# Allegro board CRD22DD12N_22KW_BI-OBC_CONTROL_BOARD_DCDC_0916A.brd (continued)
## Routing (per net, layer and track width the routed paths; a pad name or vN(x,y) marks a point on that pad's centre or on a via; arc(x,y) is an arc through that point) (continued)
DCPWM2A_2L: length 20.6
  TOP w0.152: v1(62.23,35.43) 61.66,34.86 60.64,34.86 60.07,34.29 U58.2
  BOTTOM w0.152: v1(62.23,35.43) 62.23,36.2 65.41,39.37 65.41,47 J3.5
DCPWM2A_2LL: length 30.2
  TOP w0.152: U58.1 60.68,35.56 60.96,35.84 v1(60.96,36.83) ; v1(43.69,41.78) 43.31,41.4 43.31,40.26 43.56,40.01 43.56,38.1 43.43,37.98 R421.2
  ART03 w0.127: v1(60.96,36.83) 60.12,36.83 57.43,39.52 45.44,39.52 44.42,40.54 44.42,41.05 v1(43.69,41.78)
  BOTTOM w0.152: U28.166 43.22,41.31 v1(43.69,41.78)
DCSHORT: length 38.6
  ART03 w0.127: v1(53.21,36.83) 54.79,36.83 56.51,35.11 57.99,35.11 60.58,32.51 63.63,32.51 69.22,38.1 v1(69.22,38.23)
  BOTTOM w0.152: v1(69.22,38.23) 69.85,37.59 69.85,33.78 69.98,33.66 73.28,33.66 73.78,33.15 R505.2 C464.1 U61.4 ; v1(53.21,36.83) 52.65,36.27 52.65,35.66 52.3,35.31 51.44,35.31 50.91,34.79 U28.5
DCVOLT1: length 8.4
  TOP w0.152: C455.2 R491.2 91.72,23.01 92.05,23.01 92.66,23.62 v1(92.66,24.03)
  BOTTOM w0.152: U44.1 93.98,25.97 93.62,25.61 92.49,25.61 91.64,24.77 R482.1 92.3,24.03 v1(92.66,24.03)
IOUT_ADC: length 94.2
  TOP w0.152: v1(58.14,10.59) 58.14,14.76 R607.1
  ART03 w0.127: v1(58.14,10.59) 57.33,9.78 55.37,9.78 54.61,10.54 54.61,11.56 53.62,12.55 39.22,12.55 38.61,11.94 38.61,11.18 36.6,9.17 25.76,9.17 22.35,12.57 18.41,12.57 14.1,16.89 14.1,39.12 18.16,43.18 18.16,48.01 J2.14
OUTPUT_OC: length 53.7
  TOP w0.152: v1(21.6,46.99) 20.96,46.99 J2.16 14.92,47.32 14.92,41.85 15.88,40.89 D95.3
  ART03 w0.127: v1(21.6,46.99) 22.23,46.35 29.21,46.35 34.16,41.4 37.08,41.4 38.53,39.95 40.64,39.95 42.71,37.88 v1(52.1,37.88)
  BOTTOM w0.152: U28.2 51.02,36.28 51.43,36.7 51.43,37.21 v1(52.1,37.88)
OUTPUT_OC_17227068: length 1.3
  TOP w0.152: R691.2 R689.2
P_ADREF3.2V: length 13.6
  TOP w0.508: C551.2 42.55,14.94 v1(42.9,15.29) ; v1(48.26,20.19) 48.39,20.32 C559.2 C558.2 ; C549.2 45.09,14.86 v1(44.71,15.23)
  BOTTOM w0.254: v1(42.9,15.29) 43.22,14.98 U28.55 ; v1(44.71,15.23) 44.22,14.73 U28.53 ; U28.35 48.67,19.79 v1(48.26,20.19) ; v1(48.26,18.03) 48.26,18.16 48.88,18.79 U28.37
  vias: v1(50.16,3.81)
P_SCL: length 32.7
  ART03 w0.127: v1(46.74,41.78) 47.24,41.27 48.51,41.27 48.86,40.93 58.38,40.93 60.83,38.48 64.9,38.48 65.79,39.37 v1(66.67,39.37)
  BOTTOM w0.152: U32.6 65.41,33.78 66.37,34.75 66.37,35.13 R438.1 67.21,35.44 67.44,35.66 67.44,38.61 v1(66.67,39.37) ; v1(46.74,41.78) 47.32,41.2 47.32,39.62 47.22,39.51 U28.174
P_SDA: length 25.4
  ART03 w0.127: v1(63.5,34.29) 63.5,35.56 61.21,37.85 60.33,37.85 58.01,40.16 47.2,40.16 v1(46.71,40.64)
  BOTTOM w0.152: U32.5 64.14,33.66 v1(63.5,34.29) 63.5,34.67 64.26,35.44 R437.1 ; v1(46.71,40.64) U28.173
P_WD_GREEN: length 13.4
  TOP w0.152: v1(40.64,42.55) 41.02,42.55 41.73,43.25 D102.2
  BOTTOM w0.152: v1(40.64,42.55) 40.31,42.87 36.96,42.87 35.96,41.87 33.05,41.87 31.71,40.54 U28.143
P_WD_RED: length 16.9
  TOP w0.152: D103.2 43.87,43.25 44.7,42.42 v1(44.7,42.29)
  BOTTOM w0.152: v1(44.7,42.29) 44.32,42.67 42.19,42.67 41.55,42.04 40.13,42.04 39.72,42.44 37.25,42.44 36.18,41.38 33.34,41.38 32.22,40.26 U28.144
PCS_ADC: length 10.9
  TOP w0.152: R602.2 40.01,7.5 40.64,8.13 v1(40.64,8.89)
  BOTTOM w0.152: U28.58 41.71,10.29 41.91,10.09 D90.3 41.91,8.64 41.78,8.51 41.02,8.51 v1(40.64,8.89) R606.1 C596.1
PCS_ADC1: length 8.2
  BOTTOM w0.152: C597.1 36.58,8.89 R606.2 37.98,9.53 39.12,10.67 40.77,10.67 41.22,11.12 U28.59
PWM1A: length 43.1
  TOP w0.152: U62.8 65.66,38.1 66.42,38.86 67.06,38.86 67.18,38.99 67.18,40.13 v1(66.67,40.64)
  ART03 w0.152: J2.1 39.38,48.9 62.1,48.9 67.18,43.81 67.18,41.15 v1(66.67,40.64)
PWM1AA: length 27.5
  TOP w0.152: U62.9 64.39,39.37 63.75,40.01 62.48,40.01 62.23,40.26 62.23,42.55 v1(62.87,43.18) ; R414.2 v1(53.34,34.29)
  BOTTOM w0.152: v1(62.87,43.18) 61.14,43.18 57.76,39.8 57.76,35.49 56.51,34.24 53.39,34.24 v1(53.34,34.29) 52.68,33.63 51.94,33.63 51.71,33.4 51.71,33.05 50.95,32.28 U28.10
PWM1B: length 41.2
  TOP w0.152: U62.10 65.61,40.64 66.67,41.71 v1(66.67,41.91)
  ART03 w0.152: v1(66.67,41.91) 66.67,43.18 61.59,48.26 39.19,48.26 35.86,51.59 34.15,51.59 J2.3
PWM1BB: length 23
  TOP w0.152: v1(62.87,41.91) U62.11 ; R415.2 53.21,33.02 v1(53.09,33.15)
  BOTTOM w0.152: U28.12 51.22,31.28 v1(53.09,33.15) 53.9,33.96 56.63,33.96 58.17,35.5 58.17,39.37 60.71,41.91 v1(62.87,41.91)
PWM1C: length 38.8
  TOP w0.152: v1(60.96,44.45) 61.59,44.45 62.1,43.94 63.02,43.94 63.78,43.18 U62.12
  ART03 w0.152: v1(60.96,44.45) 58.42,46.99 37.21,46.99 34.11,50.09 34.11,50.7 33.38,51.44 31.76,51.44 J2.5
PWM1CC: length 29.4
  TOP w0.152: v1(51.94,30.79) 52.25,30.48 R416.2 R610.2 ; U62.13 v1(62.87,44.45)
  BOTTOM w0.152: U28.13 v1(51.94,30.79) 51.94,31.27 54.36,33.68 56.77,33.68 58.57,35.48 58.57,39.04 60.83,41.3 63.14,41.3 63.5,41.66 63.5,43.81 v1(62.87,44.45)
PWM1D: length 38.8
  TOP w0.152: U62.6 58.8,39.37 56.52,41.66 v1(56.52,41.91)
  ART03 w0.152: J2.7 27.94,52.07 29.02,50.99 29.02,48.83 34.04,43.81 54.61,43.81 v1(56.52,41.91)
PWM1DD: length 22.3
  TOP w0.152: R611.2 R417.2 50.95,30.48 51.84,29.59 v1(51.94,29.59) ; U62.5 v1(60.96,40.64)
  BOTTOM w0.152: v1(60.96,40.64) 58.85,38.53 58.85,35.37 56.88,33.4 54.47,33.4 52.51,31.44 52.51,30.16 v1(51.94,29.59) 51.69,29.59 51,30.28 U28.14
PWM1E: length 41.4
  TOP w0.152: U62.4 v1(57.78,41.91)
  ART03 w0.152: J2.9 26.53,53.85 28.45,53.85 29.02,53.28 29.02,51.75 29.4,51.37 29.4,49.59 34.54,44.45 55.24,44.45 v1(57.78,41.91)
PWM1EE: length 25.7
  TOP w0.152: U62.3 60.81,43.18 61.47,42.52 61.47,39.88 v1(60.96,39.37)
  BOTTOM w0.152: U28.22 51.05,26.28 51.31,26.54 51.31,26.8 51.69,27.18 52.21,27.18 52.59,27.56 52.59,29.69 52.83,29.94 52.83,31.37 54.56,33.1 56.98,33.1 59.13,35.25 59.13,37.92 60.58,39.37 v1(60.96,39.37)
PWM1F: length 43.2
  TOP w0.152: U62.2 v1(57.78,44.45)
  ART03 w0.152: J2.11 24.38,54.23 28.83,54.23 29.4,53.66 29.4,52.13 30.1,51.44 30.91,51.44 31.62,50.72 31.62,48.9 34.67,45.85 56.39,45.85 v1(57.78,44.45)
PWM1FF: length 32.8
  TOP w0.152: U62.1 v1(60.96,45.72)
  BOTTOM w0.152: U28.23 51.31,25.79 51.56,26.04 52.32,26.04 52.91,26.62 52.91,29.57 53.19,29.84 53.19,31.32 54.69,32.82 56.86,32.82 57.09,32.82 57.55,33.27 57.56,33.27 59.41,35.13 59.41,37.57 60.58,38.73 61.21,38.73 61.53,39.05 61.53,39.94 62.61,41.02 63.5,41.02 64.01,41.53 64.01,44.32 62.61,45.72 v1(60.96,45.72)
RLYCTRL1: length 51
  TOP w0.152: v1(63.52,30.52) 63.52,30.51 63.5,30.51 63.5,30.48 U58.10
  ART03 w0.152: J2.2 38.11,47.62 60.83,47.62 63.75,44.7 63.75,40.26 v1(62.87,39.37)
  BOTTOM w0.152: v1(63.52,30.52) 62.8,31.24 60.36,31.24 60.07,31.53 60.07,37.08 60.77,37.78 61.53,37.78 62.87,39.12 v1(62.87,39.37)
RLYCTRL2: length 52.4
  TOP w0.152: v1(63.5,29.21) 63.5,28.22 63.78,27.94 U58.8
  ART03 w0.152: v1(62.87,40.51) 57.03,46.35 36.84,46.35 J2.4
  BOTTOM w0.152: v1(63.5,29.21) 62.87,29.84 62.87,30.48 62.48,30.86 60.2,30.86 59.69,31.37 59.69,37.24 60.61,38.16 61.28,38.16 61.98,38.86 61.98,39.61 v1(62.87,40.51)
RLYCTRL11: length 47.2
  TOP w0.152: v1(62.23,30.23) 62.23,30.48 63.5,31.75 U58.11 ; R703.2 27.43,40.77 v1(27.3,40.64)
  ART03 w0.127: v1(57.63,31.62) 57,32.26 45.95,32.26 40.36,37.85 29.46,37.85 27.3,40.01 v1(27.3,40.64)
  BOTTOM w0.152: v1(27.3,40.64) 26.71,40.05 U28.133 ; v1(62.23,30.23) 61.98,30.48 59.31,30.48 58.59,31.2 58.05,31.2 v1(57.63,31.62)
RLYCTRL22: length 46.5
  TOP w0.152: v1(62.23,29.34) 62.61,29.72 63.88,29.72 64.39,29.21 U58.9 ; R707.2 26.8,36.2 v1(27.46,36.86)
  ART03 w0.127: v1(27.46,36.86) 27.94,37.34 40.28,37.34 46.38,31.24 49.73,31.24 49.99,31.5 56.79,31.5 v1(57.63,30.66)
  BOTTOM w0.152: v1(57.63,30.66) 57.8,30.49 58.66,30.49 59.25,29.91 60.26,29.91 60.83,29.34 v1(62.23,29.34) ; v1(27.46,36.86) 27.39,36.79 U28.132
SR-PWM-A: length 35.2
  TOP w0.152: U59.12 63.91,22.23 v1(63.25,22.89)
  ART03 w0.127: J3.9 67.69,49.79 67.69,42.8 70.38,40.11 70.38,38.63 62.87,31.11 62.87,28.19 61.72,27.05 61.72,23.88 62.1,23.5 62.64,23.5 v1(63.25,22.89)
SR-PWM-AA: length 20.8
  TOP w0.152: 65.12,23.5 64.54,23.5 63.9,24.14 63.9,24.62 63.72,24.8 63.19,24.8 62.9,25.09 62.9,25.85 62.71,26.04 v1(59.69,26.04) ; R422.2 52.45,29.21 v1(51.94,28.7)
  ART03 w0.508: v1(51.94,28.7) 53.09,28.7 53.85,27.94 57.78,27.94 v1(59.69,26.04)
  BOTTOM w0.152: v1(51.94,28.7) 51.53,28.28 U28.18
SR-PWM-B: length 35.9
  TOP w0.152: v1(62.23,25.53) 62.23,24.99 60.73,23.5 59.59,23.5
  ART03 w0.127: v1(62.23,25.53) 62.23,26.8 64.77,29.34 64.77,32.38 70.74,38.36 70.74,40.51 68.45,42.8 68.45,51.57 J3.10
SR-PWM-BB: length 26.4
  TOP w0.152: v1(61.07,25.53) 61.07,25.13 60.71,24.77 U59.1 ; v1(53.34,37.85) 53.47,37.85 R423.2
  ART03 w0.127: v1(53.34,37.85) 52.68,37.19 52.68,36.6 52.95,36.33 54.57,36.33 56.36,34.54 57.97,34.54 60.1,32.42 60.1,29.86 61.47,28.49 61.47,27.43 61.07,27.04 v1(61.07,25.53)
  BOTTOM w0.152: U28.1 50.68,36.79 50.95,37.06 50.95,37.62 51.79,38.46 52.73,38.46 v1(53.34,37.85)
SR-PWM-C: length 35.8
  TOP w0.152: v1(63.25,24.13) 62.74,23.62 62.74,22.47 62.59,22.32 62.07,22.32 60.71,20.95 U59.4
  ART03 w0.127: J3.11 71.12,48.9 71.12,38.23 65.28,32.38 65.28,29.08 62.87,26.67 62.87,24.51 v1(63.25,24.13)
SR-PWM-CC: length 26.8
  TOP w0.152: v1(52.07,36.83) R424.2 ; U59.3 60.83,22.23 61.47,22.86 v1(62.23,22.86)
  ART03 w0.127: v1(62.23,22.86) 60.58,24.51 60.58,27.28 59.44,28.42 59.44,32.52 57.81,34.15 55.94,34.15 54.01,36.08 52.82,36.08 v1(52.07,36.83)
  BOTTOM w0.152: v1(52.07,36.83) 51.44,36.2 51.44,35.81 50.91,35.28 U28.4
SR-PWM-D: length 41.6
  TOP w0.152: v1(63.5,21.59) 62.61,20.7 62.61,19.81 61.21,18.41 U59.6
  ART03 w0.127: J3.12 71.5,51.06 71.5,38.1 65.79,32.38 65.79,28.83 63.5,26.54 63.5,25.91 64.35,25.06 64.35,22.46 63.87,21.98 63.87,21.96 v1(63.5,21.59)
SR-PWM-DD: length 28.3
  TOP w0.152: v1(62.1,20.19) 61.59,19.68 U59.5 ; R425.2 54.46,35.59 v1(53.19,35.59)
  ART03 w0.127: v1(53.19,35.59) 53.64,35.59 55.45,33.78 57.66,33.78 58.93,32.51 58.93,28.22 60.2,26.95 60.2,22.1 v1(62.1,20.19)
  BOTTOM w0.152: v1(53.19,35.59) 52.97,35.59 52.77,35.38 52.77,35.38 52.36,34.98 51.69,34.98 51,34.28 U28.6
TCK_P: length 8.6
  TOP w0.152: R407.2 R408.2 33.66,9.02 33.05,9.63 33.05,10.36 32.64,10.77 30.64,10.77 v1(29.86,11.54)
  BOTTOM w0.152: v1(29.86,11.54) 29.94,11.54 30.22,11.82 U28.81
TDI_P: length 18.2
  TOP w0.152: R405.2 v1(29.84,6.35) 29.2,5.7 28.44,5.7 27.92,5.18 27.92,3.2 J5.3
  BOTTOM w0.152: v1(29.84,6.35) 30.38,5.82 32.23,5.82 32.71,6.29 32.71,9.43 33.03,9.74 33.03,10.37 32.22,11.18 U28.77
TDO_P: length 13.9
  TOP w0.152: R406.2 32.38,6.99 v1(31.75,6.35) 33.01,5.09 33.01,3.19 J5.7
  BOTTOM w0.152: v1(31.75,6.35) 31.71,6.39 U28.78
TEST: length 4
  BOTTOM w0.152: U28.140 30.22,39.87 30.61,40.26 30.61,40.77 DAC_6.1
TMS_P: length 15.7
  TOP w0.152: R404.2 v1(26.04,6.35) 25.18,5.5 25.18,3.39 J5.1
  BOTTOM w0.152: v1(26.04,6.35) 29.24,9.56 29.24,10.44 29.67,10.87 30.07,10.87 30.71,11.51 U28.80
VO1+: length 16.3
  BOTTOM w0.508: J4.1 90.05,41.41 R574.1
VO2+: length 11.9
  TOP w0.508: J4.3 84.71,49.28 84.71,44.83 88.27,41.27 R573.1
VP3.3A: length 55.6
  TOP w0.381: C521.1 v1(48.26,19.05)
  TOP w0.508: D127.2 42.86,6.89 42.7,6.73 v1(41.91,6.73) ; C550.2 v1(43.81,15.24) ; v1(57.4,27.05) 57.96,27.61 57.96,29.41 v1(57.61,29.77) ; v1(54.29,6.05) D89.2
  ART03 w0.381: v1(51.44,6.1) 50.8,6.73 48.9,6.73 47.88,5.71 42.93,5.71 v1(41.91,6.73) 41.53,7.11 35.05,7.11 v1(34.19,6.25)
  ART03 w0.508: v1(57.4,27.05) 56.77,26.42 56.77,24.7 v1(57.66,23.82)
  BOTTOM w0.254: U28.54 43.71,15.14 v1(43.81,15.24) ; v1(48.26,19.05) 48.49,19.28 U28.36
  BOTTOM w0.381: D115.2 52.39,7.69 52.83,8.13 53.82,8.13 54.07,8.38 54.74,8.38 55.07,8.05 55.07,6.6 54.51,6.05 v1(54.29,6.05) 55.51,4.83 56.44,4.83 ; v1(34.19,6.25) 33.89,6.25 33.34,6.79 D86.2
  BOTTOM w0.508: D85.2 57.34,26.99 v1(57.4,27.05) ; v1(57.61,29.77) 57.15,29.77 56.75,30.17 D84.2 ; D115.2 52.39,6.85 51.64,6.1 v1(51.44,6.1) ; D92.2 v1(57.66,23.82) 57.28,23.43 57.28,21.31 v1(57.53,21.06) ; v1(41.91,6.73) 41.83,6.65 41.15,6.65 40.96,6.84 D90.2
  vias: v1(60.83,10.79) v1(61.85,10.79)
VP3.3D: length 163.3
  TOP w0.381: C540.1 26.67,16.63 v1(26.67,16.51) ; D95.2 v1(16.82,39.5) 16.76,39.5 16.59,39.33 15.58,39.33 15.4,39.5 14.48,39.5 13.97,38.99 13.97,37.08 13.21,36.32 ; 63.88,0.76 48.39,0.76 47.11,2.03 R412.1 R411.1 ; D124.2 26.35,38.8 26.16,38.99 25.59,38.99 v1(25.4,38.8) ; D125.2 v1(23.17,39.5) ; D126.2 v1(20,39.5) ; C541.2 v1(27.94,15.24) ; R691.1 v1(15.88,45.09)
  TOP w0.508: C520.1 50.92,40.51 ; R404.1 v1(26.04,10.16) ; R406.1 v1(32.38,10.16) ; J18.2 20.95,8.29 v1(20.95,9.84) C406.2 ; C539.1 v1(26.67,20.32) ; R327.2 31.11,40.64 ; C552.1 C557.2 v1(48.26,24.13) ; v1(36.2,10.16) 35.94,9.91 35.94,8 35.43,7.5 R407.1 ; C545.2 v1(34.92,15.24) ; 13.21,36.32 11.3,34.41 R537.2 ; C534.1 v1(26.67,31.11) ; R598.1 77.91,8.41 J17.2 ; C536.1 v1(26.67,28.57) ; C555.2 v1(48.26,27.94) ; v1(48.26,31.75) 48.26,32 49.28,33.02 C553.2 ; C524.2 v1(40.01,36.83) ; v1(20.57,26.54) 20.57,27.3 R546.2 21.34,27.94 21.97,27.3 v1(21.97,26.54) ; D104.2 49.46,43.25 v1(49.53,43.18) ; R687.1 v1(20.32,45.09) ; C523.2 44.32,36.96 v1(44.2,36.83) ; C528.2 v1(33.66,36.83) ; R685.1 v1(22.23,45.09) ; v1(34.92,36.83) C527.2 ; R540.1 5.59,21.82 v1(5.43,21.66) ; v1(26.67,32.89) 26.16,32.38 C533.1 ; C546.2 v1(36.83,15.24) ; R405.1 v1(29.84,10.16) ; v1(39.37,15.24) 38.61,15.24 38.23,14.86 C547.2 ; C537.1 v1(26.67,27.3) ; C529.2 29.84,37.08 v1(29.59,36.83) ; R688.1 v1(25.4,45.09) ; C544.2 v1(33.66,15.24) ; C538.1 v1(26.67,23.5) ; C542.2 v1(29.84,15.24) ; R400.2 37.47,40.64 ; C531.1 v1(26.67,34.92) ; R409.2 v1(31.11,10.16)
  BOTTOM w0.254: U28.68 36.71,15.12 v1(36.83,15.24) ; U28.106 26.38,23.79 v1(26.67,23.5) ; v1(48.26,31.75) 48.3,31.79 U28.11 ; v1(29.59,36.83) 29.22,37.21 U28.138 ; U28.62 39.71,14.9 v1(39.37,15.24) ; v1(26.67,15.24) 26.71,15.2 U28.88 ; v1(44.2,36.83) 44.22,36.85 U28.168 ; U28.152 36.22,37.82 35.23,36.83 v1(34.92,36.83) ; v1(26.67,34.92) 26.03,34.28 U28.127 ; U28.125 26.28,33.28 v1(26.67,32.89) ; U28.99 26.63,20.28 v1(26.67,20.32) ; U28.3 48.49,35.79 ; U28.75 33.22,14.8 v1(33.66,15.24) ; v1(48.26,27.94) 48.92,27.28 U28.20 ; U28.26 48.41,24.28 v1(48.26,24.13) ; U28.114 26.19,27.79 v1(26.67,27.3) ; v1(26.67,16.51) 26.44,16.28 U28.91 ; U28.119 26.22,30.28 26.67,30.73 v1(26.67,31.11) 26.04,31.11 25.71,30.79 U28.120 ; v1(29.84,15.24) 29.71,15.11 U28.82 ; 48.26,29.79 U28.15 ; v1(26.67,28.57) 26.46,28.79 U28.116 ; U28.72 34.71,15.03 v1(34.92,15.24) ; U28.147 33.71,36.89 v1(33.66,36.83) ; v1(40.01,36.83) 39.71,37.12 U28.159
  BOTTOM w0.508: R437.2 R438.2 v1(66.67,38.1) ; v1(70.99,35.31) 71,35.31 71.5,34.8 R502.1 ; C405.1 78.11,8.22 J17.2 ; 67.94,33.18 67.94,31.62 68.96,30.6 C396.1 70.36,30.6 v1(71.12,29.84) ; R505.1 v1(71.12,32.38) ; R439.2 67.94,37.59 v1(67.94,38.1)
  vias: v1(3.81,46.35) v1(3.81,45.09) v1(5.08,46.35) v1(5.08,45.09) v1(6.35,46.35) v1(6.35,45.09) v1(6.35,11.43) v1(6.35,10.16) v1(6.35,8.89) v1(7.62,11.43) v1(7.62,10.16) v1(7.62,8.89) v1(27.94,16.51) v1(29.84,16.51) v1(49.53,41.91) v1(51.44,41.91) v1(52.7,41.91) v1(53.98,41.91) v1(66.04,5.08) v1(67.31,5.08) v1(68.58,5.08) v1(69.85,5.08) v1(71.75,1.27) v1(73.03,1.27) v1(74.3,1.27)
VP+5V: length 37.3
  TOP w0.381: R549.2 v1(70.48,33.02) ; v1(69.22,26.42) 68.58,27.05 60.58,27.05 60.33,26.8 58.99,26.8 58.55,26.35 U55.1 53.66,26.35 53.34,26.67 53.34,27.51 53.77,27.94 C494.1
  TOP w0.508: v1(9.02,30.86) 9.01,30.86 R536.2 ; R612.2 v1(70.48,45.72) ; v1(69.22,26.42) 69.34,26.29 R550.2
  BOTTOM w0.381: v1(74.3,37.47) 71.63,40.13 71.63,44.45 70.48,45.59 v1(70.48,45.72)
  BOTTOM w0.508: R594.2 71.38,26.04 70.87,25.52 R595.2 69.85,25.78 v1(69.22,26.42)
  vias: v1(6.1,32.77) v1(6.1,31.62) v1(6.1,30.48) v1(7.74,30.86) v1(10.29,30.86) v1(11.3,30.86) v1(52.7,5.08) v1(53.98,5.08) v1(53.98,3.81)
VS+5V: length 28.8
  TOP w0.508: R507.1 v1(97.91,32.26) ; R493.1 95.4,23.12 95.89,23.6 v1(95.89,23.75) ; v1(98.3,23.75) 97.91,24.13 R492.2 ; R496.1 v1(92.59,34.42)
  TOP w0.762: J4.7 88.9,43.56 91.56,40.9 v1(91.56,38.1)
  ART03 w0.508: v1(88.9,35.56) 92.2,35.56
  BOTTOM w0.508: R503.1 91.69,32.89 92.2,32.89 v1(92.71,32.38) ; R500.1 v1(91.56,38.1) R597.1 ; R593.2 91.87,26.04 v1(92.53,26.7) ; R592.2 v1(88.9,20.95) ; R569.1 v1(88.9,35.56)
X1: length 9.1
  BOTTOM w0.254: Y1.1 17.62,33.08 20.13,33.08 C371.2 21.2,32.9 R221.1 21.82,32.28 U28.123
X2: length 9.3
  BOTTOM w0.254: Y1.2 18.44,31.24 C254.2 21.34,31.24 R221.2 21.64,30.99 21.94,31.28 U28.121
XRS: length 28
  TOP w0.508: R547.1 10.92,28 11.18,27.74 11.18,25.32 10.29,24.43 10.29,23.5 R541.1 15.89,23.5 19.82,27.43 19.82,30.46 20.1,30.74 R546.1 21.71,31.24 C519.1 21.71,33.78 v1(21.72,33.78)
  BOTTOM w0.254: U28.124 23.73,32.79 23.37,33.15 22.35,33.15 v1(21.72,33.78)
N16777869: length 9.4
  TOP w0.152: J5.11 J5.9 35.54,3.19 35.54,5.61 R408.1
N16778586: length 5.8
  TOP w0.152: R700.2 48.97,12.58 C702.1 R701.2 v1(46.35,11.43)
  BOTTOM w0.152: v1(46.35,11.43) 46.22,11.57 U28.49
N16779815: length 3.6
  TOP w0.152: v1(30.66,36.83) 31.11,37.29 R327.1
  BOTTOM w0.152: U28.139 29.71,37.77 v1(30.66,36.83)
N16809513: length 6.4
  TOP w0.152: J5.5 30.5,3.15 30.5,6.3 31.11,6.91 R409.1
N16810933: length 3.9
  TOP w0.152: J5.13 42.55,2.54 R412.2
N16810951: length 3.9
  TOP w0.152: R411.2 42.55,3.81 J5.14
N16833081: length 2.1
  TOP w0.152: D102.1 R443.1
N16833084: length 2.3
  TOP w0.152: R444.1 43.81,46.87 D103.1
N16833087: length 2.6
  TOP w0.152: D104.1 45.72,46.23 R445.1
N16835391: length 32.7
  TOP w0.152: v1(69.85,15.37) 71.12,14.1 71.12,10.41 73.28,8.26 J17.1
  ART03 w0.127: v1(58.09,20.35) 59.28,20.35 62.23,17.4 67.82,17.4 v1(69.85,15.37)
  BOTTOM w0.152: v1(58.09,20.35) 57.45,20.35 56.59,21.21 R447.1 ; R446.1 C407.1 J17.1
N16836592: length 56.4
  TOP w0.152: J18.1 18.41,9.53 19.05,10.16 R448.1 ; R448.1 C409.1 ; R448.1 19.56,11.31 19.94,11.68 19.94,14.47 21.25,15.78 26.91,15.78 27.26,16.12 27.26,17.09 27.26,17.1 v1(27.94,17.78)
  ART03 w0.127: v1(58.01,21.79) 58,21.78 54.74,21.78 52.26,19.3 51.82,19.3 51.56,19.56 45.36,19.56 44.32,18.52 28.68,18.52 v1(27.94,17.78)
  BOTTOM w0.152: v1(58.01,21.79) 58.17,21.95 58.17,25.4 59.05,26.29 59.05,26.54 R449.1
N16848574: length 4.1
  BOTTOM w0.508: U43.2 88.01,24.77 88.14,24.64 89.92,24.64 R482.2 C446.1
N16848598: length 4.6
  BOTTOM w0.381: R593.1 C445.2
  BOTTOM w0.508: C445.2 89.41,27.3 88.14,26.04 U43.1
N16848614: length 4.8
  TOP w0.508: v1(74.93,25.4) 75.44,24.89 C447.2
  BOTTOM w0.152: R594.1 74.3,26.04 v1(74.93,25.4) 75.13,25.4 75.77,26.04 U43.8
N16848642: length 2.8
  BOTTOM w0.152: R483.1 U43.7
N16848644: length 12.7
  TOP w0.152: v1(66.8,16.89) 66.93,16.89 v1(71.12,21.08)
  BOTTOM w0.152: U45.3 65.41,17.4 65.91,16.89 v1(66.8,16.89) ; v1(71.12,21.08) 72.26,22.23 C448.2 R484.2 R483.2
N16848814: length 4.5
  BOTTOM w0.152: 76.54,23.5 75.18,23.5 74.68,22.99 74.68,21.85 R485.1
N16848816: length 7.8
  BOTTOM w0.152: R485.2 72.26,20.95 71.12,19.81 R486.1 C449.1 69.22,19.17 68.83,19.56 67.31,19.56 66.67,18.92 U45.2
N16848832: length 29
  TOP w0.152: R487.1 55.88,10.57 v1(55.52,10.92)
  ART03 w0.127: v1(55.52,10.92) 56.08,11.48 58.6,11.48 60.05,10.03 69.22,10.03 70.99,11.81 70.99,15.49 v1(69.85,16.64)
  BOTTOM w0.152: R486.2 C449.2 v1(69.85,16.64) 68.96,16.64 67.94,17.65 67.94,18.25
N16848970: length 3.4
  BOTTOM w0.152: U44.6 96.52,20.5 96.22,20.19 95.5,20.19 95.25,20.45 U44.7
N16848978: length 9.7
  TOP w0.152: C454.1 R488.2 C453.2 R489.2 R492.1 96.4,24.25 v1(96.9,23.75)
  BOTTOM w0.152: v1(96.9,23.75) 96.8,23.75 96.52,24.03 U44.3
N16848994: length 10.6
  TOP w0.152: C455.1 R491.1 91.97,24.25 v1(92.71,24.99) 93.07,24.64 R494.2 ; R494.2 93.47,24.76 C454.2 ; R494.2 R493.2
  BOTTOM w0.152: v1(92.71,24.99) 94.59,24.99 95.25,25.66 U44.2
N16849016: length 4.4
  BOTTOM w0.152: U44.8 93.98,22.07 93.83,22.23 C457.1 R592.1
N16851028: length 3.3
  BOTTOM w0.152: U45.6 65.41,24.61 65.56,24.77 66.52,24.77 66.67,24.61 U45.7
N16851046: length 4.3
  BOTTOM w0.152: C451.1 R595.1 69.21,24.01 68.83,24.38 68.2,24.38 67.94,24.13 67.94,23.66
N16853569: length 5.3
  TOP w0.152: C460.1 C458.1 R495.2 95.76,34.41 v1(95.89,34.29)
  BOTTOM w0.152: U48.3 v1(95.89,34.29)
N16853931: length 10.1
  TOP w0.152: C460.2 97.28,38.61 96.82,39.07 94.51,39.07 94.1,38.66 R497.1 C459.1 R496.2 94.1,34.8 v1(94.61,34.29)
  BOTTOM w0.152: U48.2 v1(94.61,34.29)
N16853972: length 7.6
  BOTTOM w0.152: 86.94,33.66 88.39,33.66 89.03,34.29 90.81,34.29 91.56,35.05 R569.2 93.18,35.56 U48.1
N16854025: length 17.4
  ART03 w0.508: v1(88.9,29.72) 87.76,30.86 87.76,36.83 89.03,38.1 v1(90.17,38.1)
  BOTTOM w0.508: v1(88.9,29.72) 89.28,30.1 C462.1 C566.1 91.44,30.1 92.08,29.46 93.09,29.46 93.34,29.72 U48.8 ; R597.2 90.05,38.22 v1(90.17,38.1)
N16854569: length 3.4
  BOTTOM w0.152: U60.1 88.39,36.2 89.03,36.83 R500.2
N16855013: length 10.3
  TOP w0.152: C466.2 93.47,32.01 94.23,32.77 95.89,32.77 v1(96.39,32.26) 96.4,32.26 R507.2 C467.1 R508.1
  BOTTOM w0.152: U48.5 97.16,31.5 v1(96.39,32.26)
N16855828: length 6
  TOP w0.152: R506.2 C465.1 C466.1 94.99,31.87 v1(95.38,32.26)
  BOTTOM w0.152: v1(95.38,32.26) 95.89,31.75 U48.6
N16855912: length 9.3
  BOTTOM w0.152: U61.2 87.86,28.57 88.29,28.14 89.61,28.14 90.05,28.57 93.85,28.57 94.61,29.34 U48.7
N16855916: length 3.9
  BOTTOM w0.152: U61.1 88.14,31.11 R503.2
N16860426: length 83.4
  TOP w0.152: C472.1 R598.2 ; C472.1 75.63,13.34 v1(75.25,12.95) ; C472.1 C471.1
  ART03 w0.127: v1(18.41,24.13) 18.41,17.53 21.97,13.97 21.97,13.46 25.91,9.53 36.32,9.53 37.59,10.79 37.59,11.94 38.61,12.95 53.85,12.95 54.99,11.81 54.99,10.67 55.37,10.29 55.88,10.29 56.74,11.15 58.29,11.15 59.79,9.65 69.7,9.65 70.87,10.82 73.11,10.82 v1(75.25,12.95)
  BOTTOM w0.152: v1(18.41,24.13) R514.1 R515.1 ; U53.1 75.44,11.43 75.25,11.62 v1(75.25,12.95)
N16860580: length 10.1
  TOP w0.508: v1(91.44,11.56) 91.31,11.56 90.83,12.04 90.32,12.04 R516.2 C474.1 C475.1 C473.1
  BOTTOM w0.508: v1(91.44,11.56) 91.31,11.43 U53.8
N16860640: length 8.9
  TOP w0.152: v1(84.45,13.97) D110.2 D112.1
  BOTTOM w0.152: T1.2 90.08,13.97 U53.7 v1(84.45,13.97)
N16861242: length 8.3
  BOTTOM w0.152: J11.2 94.74,8.73 R517.1 96.01,12.06 98.51,12.06 98.66,12.22 T2.4
N16861249: length 9
  TOP w0.152: v1(84.45,16.51) D114.1 D113.2
  BOTTOM w0.152: v1(84.45,16.51) U53.6 90.08,16.51 T1.1
N16861268: length 7
  BOTTOM w0.152: J11.1 93.22,8.77 R517.2 93.22,11.31 95.18,13.27 T2.3
N16861373: length 4.3
  TOP w0.381: D114.2 D112.2 89.66,15.24 90.3,14.61 90.77,14.61 D111.2
N16900365: length 4.1
  TOP w0.508: Q1.1 7.93,33.72 8.76,32.9 R538.2 R537.1
N16900541: length 7.3
  TOP w0.508: Q1.3 6.99,30.36 R536.1 7.5,28.82 C505.1 8.4,27.92 v1(8.4,27.46)
  BOTTOM w0.381: U57.7 8.58,27.64 v1(8.4,27.46)
N16908509: length 4.6
  TOP w0.508: v1(7.75,24.51) 7.41,24.51 7.11,24.2 R540.2 R541.2
  BOTTOM w0.381: U57.19 7.93,24.33 v1(7.75,24.51)
N16935004: length 2.7
  TOP w0.508: R547.2 9.4,27.48 v1(9.41,27.47)
  BOTTOM w0.381: v1(9.41,27.47) 9.23,27.65 U57.8
N17022031: length 6.6
  TOP w0.152: C561.1 R549.1 C562.1 C560.1 U58.14
N17025421: length 6.5
  TOP w0.152: U59.14 R550.1 C563.1 C565.1 C564.1
N17096901: length 14.1
  TOP w0.381: R573.2 90.14,35.46 90.14,27.4 R133.1 C237.2 91.55,27.32 93.46,27.32 R488.1
N17102058: length 20.4
  TOP w0.152: v1(98.42,35.56) R495.1 96.93,35.21 96.93,35.08 96.52,34.67 96.52,34.08 96.52,34.08 96.52,33.91 96.06,33.45 92.86,33.45 91.85,32.44 91.85,29.59 92.86,28.57 R506.1
  BOTTOM w0.152: R574.2 93.99,38.61 C594.1 R575.1 97.69,38.61 97.92,38.38 97.92,36.07 v1(98.42,35.56)
N17145229: length 8.6
  BOTTOM w0.152: R599.2 C595.1 43.82,8.38 42.7,8.38 42.55,8.53 42.55,10.29 42.04,10.79 42.04,11.94 42.22,12.12 U28.57
N17182974: length 88.8
  TOP w0.152: R528.1 C488.1 R58.2 51.82,11.94 v1(51.31,11.43) 51.31,11.31 R529.1
  ART03 w0.127: v1(51.31,11.43) 50.67,10.79 39.27,10.79 38.53,10.06 38.53,9.78 37.19,8.43 25.22,8.43 22,11.66 18.31,11.66 13.34,16.63 13.34,45.71 10.54,48.51 7.37,48.51 5.71,50.16 v1(5.71,50.17)
  BOTTOM w0.152: v1(5.71,50.17) 4.95,49.41 R49.1
N17183073: length 4.3
  TOP w0.152: R534.1 R532.2 53.98,20.95 54.49,20.44 C492.1 R533.1
N17183105: length 2.3
  TOP w0.152: R532.1 53.47,23.49 53.47,24.26 53.66,24.45 U55.2
N17207390: length 6.6
  TOP w0.152: U62.14 R612.1 C602.1 C600.1 C601.1
N17215412: length 10.3
  BOTTOM w0.152: U28.42 51.21,16.28 51.31,16.38 52.45,16.38 53.91,14.92 55.18,14.92 56.13,13.97 57.41,13.97 57.66,14.22 R679.1
N17215422: length 3.9
  BOTTOM w0.152: R678.1 52.07,15.88 51.94,16 51.31,16 51.09,15.79 U28.43
N17215466: length 5.4
  BOTTOM w0.152: C691.2 R681.2 ; R681.2 60.58,14.09 DAC_5.1 ; R681.2 59.69,14.86 59.18,15.37 R679.2
N17215490: length 4.5
  BOTTOM w0.152: DAC_4.1 56.39,12.58 R680.2 C690.2 R678.2
N17215663: length 9.7
  BOTTOM w0.152: R673.2 C687.2 49.02,9.01 DAC_1.1 47.22,8.03 U28.47
N17215880: length 6.3
  TOP w0.152: v1(51.56,15.49) 52.96,16.89 R607.2 C598.1
  BOTTOM w0.152: v1(51.56,15.49) 51.35,15.28 U28.44
N17228521: length 68.3
  TOP w0.152: v1(39.62,10.01) 39.61,9.99 39.2,9.99 38.81,9.6 38.81,7.75 38.56,7.5 R693.1
  ART03 w0.127: v1(39.62,10.01) 39.62,9.14 38.1,7.62 24.52,7.62 21.34,10.79 16.8,10.79 12.57,15.02 12.57,36.07 11.18,37.47 v1(8.76,37.47)
  BOTTOM w0.152: v1(8.76,37.47) 9.66,37.47 R694.1 12.69,37.97 R695.2 C698.1 R692.1
N17238784: length 75.2
  TOP w0.152: R705.2 48.97,15.16 v1(48.9,15.24)
  ART03 w0.127: v1(47.24,21.21) 47.24,21.46 48.01,22.23 52.2,22.23 53.21,23.24 58.67,23.24 59.88,22.03 59.88,21.53 61.85,19.56 62.36,19.56 62.61,19.81 62.61,20.45 63.12,20.95 63.75,20.95 64.83,22.03 64.83,26.73 66.29,28.19 66.29,32.38 71.88,37.97 71.88,46.1 80.01,54.23 84.84,54.23 J4.6
  BOTTOM w0.152: v1(47.24,21.21) 47.24,16.89 v1(48.9,15.24)
N17238858: length 13.3
  BOTTOM w0.152: R696.2 R697.2 C700.1 58.8,19.81 57.58,19.81 56.95,20.45 53.34,20.45 51.18,18.28 U28.38
N17241205: length 11.6
  BOTTOM w0.152: R698.2 R699.2 C701.1 57.78,18.54 57.78,18.5 57.68,18.4 57.68,18.19 57.47,17.97 57.47,17.97 57.15,17.65 53.85,17.65 53.34,17.14 51.56,17.14 51.42,17.28 U28.40
N17279598: length 6.4
  BOTTOM w0.152: T2.1 98.66,16.49 97.41,15.24 95.76,15.24 94.87,14.35 94.66,14.35 T1.3
N17279601: length 2.7
  BOTTOM w0.152: T2.2 96.16,16.66 95.99,16.49 T1.4
N17282960: length 55.7
  ART03 w0.127: v1(66.67,20.32) 66.17,20.83 66.17,26.8 66.93,27.56 66.93,32.51 72.26,37.85 72.26,45.21 80.9,53.85 82.69,53.85 J4.4
  BOTTOM w0.152: v1(66.67,20.32) 65.66,20.32 63.75,22.23 63.12,22.23 62.74,22.61 62.74,25.88 62.59,26.04 60.58,26.04 59.69,25.15 59.69,24.89 R704.2
N17283298: length 44.9
  ART03 w0.127: J4.2 72.64,44.08 72.64,37.72 67.44,32.51 67.44,19.94 67.06,19.56 63.75,19.56 v1(63.12,20.19)
  BOTTOM w0.152: R706.2 63.12,19.81 v1(63.12,20.19)
N16779431153: length 3.1
  TOP w0.152: R400.1 v1(37.47,36.83)
  BOTTOM w0.152: v1(37.47,36.83) 37.22,37.08 U28.154

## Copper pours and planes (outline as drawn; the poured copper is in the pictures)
AGND on TOP (solid shape): 43.45,29.63 43.45,24.1 41.65,22.3 38.9,22.3 37.89,21.29 33.32,21.29 31.64,22.97 31.64,31.9 32.32,32.58 40.5,32.58
AGND on TOP (solid shape): 14.89,15.06 14.89,10.29 15.4,9.78 15.4,3.67 15.37,3.64 15.37,1.09 14.85,0.57 0.93,0.57 0.59,0.91 0.59,11.42 0.95,11.78 3.91,11.78 4.24,11.45 4.24,8.37 3.8,7.93 2.32,7.93 1.47,7.08 1.47,2.91 2.42,1.97 10.44,1.97 11.73,3.25 11.73,15.06 12.1,15.43 14.52,15.43
AGND on TOP (solid shape): outline of 184 points within 11.83,24.07 23.18,37.21
AGND on BOTTOM (solid shape): 43.19,31.06 43.19,21.89 42.1,20.8 32.22,20.8 31.23,21.79 31.23,31.28 31.85,31.9 42.35,31.9
AGND on BOTTOM (solid shape): 53.94,2.79 53.94,0.69 53.81,0.56 45.01,0.56 44.86,0.71 44.86,1.77 45.02,1.93 48.44,1.93 48.86,1.51 52.06,1.51 52.39,1.84 52.39,2.83 52.53,2.97 53.76,2.97
AGND on BOTTOM (solid shape): 61.82,2.52 65.34,2.52 65.68,2.86 70.05,2.86 70.24,2.66 70.24,1.12 69.94,0.82 56.94,0.82 56.65,1.11 56.65,2.28 56.87,2.5 58.86,2.5 59.22,2.86 61.48,2.86
AGND on BOTTOM (solid shape): 82.1,19.81 82.1,0.85 81.82,0.57 75.45,0.57 75.26,0.76 75.26,1.38 75.55,1.66 78.71,1.66 79.62,2.57 79.62,10.76 78.92,11.46 78.92,19.73 79.18,19.99 81.92,19.99
AGND on BOTTOM (solid shape): outline of 204 points within 0.56,3.81 23.39,38.4
AGND on ART02 (solid shape): outline of 17009 points within 0.56,0.56 81.28,54.44
AGND on ART03 (solid shape): 44.15,29.09 44.15,20.5 43.63,19.98 30.48,19.98 29.8,20.66 29.8,30.38 30.36,30.94 42.29,30.94
AGND on ART03 (solid shape): outline of 195 points within 14.5,13.3 21.4,37.59
SGND on TOP (solid shape): outline of 684 points within 82.42,19.97 99.44,54.44
SGND on BOTTOM (solid shape): outline of 675 points within 85.34,22.39 99.44,54.44
SGND on ART02 (solid shape): outline of 1526 points within 82.93,19.94 99.44,54.44
VDD on TOP (solid shape): outline of 287 points within 7.66,3.28 48.64,37.21
VDD on BOTTOM (solid shape): 10.12,23.98 10.29,23.95 10.46,23.98 11.21,23.98 11.37,23.82 11.37,21.29 10.73,20.65 10.73,6.14 11.07,5.8 11.07,4.09 10.88,3.9 7.96,3.9 7.81,4.05 7.81,5.82 8.89,6.9 8.89,21.15 9.7,21.96 9.7,23.75 9.92,23.98
CAN5V_GND on TOP (solid shape): outline of 119 points within 85.98,0.61 99.44,19.4
CAN5V_GND on BOTTOM (solid shape): 99.44,0.56 89.53,0.56 89.53,1.12 89.49,1.17 89.49,7.37 88.72,8.15 86.32,8.15 85.98,8.48 85.98,10.21 86.32,10.55 90.37,10.55 91.47,9.44 91.47,7.19 91.77,6.9 96.23,6.9 96.53,7.19 96.53,11.56 99.44,11.56
CAN5V_GND on ART02 (solid shape): outline of 329 points within 83.4,0.56 99.44,19.43
CAN5V_GND on ART03 (solid shape): outline of 325 points within 83.41,0.59 99.4,19.38
P_ADREF3.2V on TOP (solid shape): outline of 338 points within 40.13,3.56 50.8,20.57
P_ADREF3.2V on BOTTOM (solid shape): 51.75,5.32 51.75,2.16 51.63,2.03 49.24,2.03 48.61,2.66 48.61,5.37 48.73,5.49 51.59,5.49
VP3.3A on BOTTOM (solid shape): 62.98,10.93 62.98,3.23 62.87,3.13 61.93,3.13 61.5,3.55 58.99,3.55 58.67,3.86 56.57,3.86 56.36,4.07 56.36,5.08 56.75,5.46 59.03,5.46 59.04,5.47 59.7,5.47 60.07,5.84 60.07,11.05 60.2,11.18 62.73,11.18
VP3.3A on ART03 (solid shape): outline of 940 points within 43.31,10.48 62.99,21.46
VP3.3D on TOP (solid shape): outline of 720 points within 48.64,0.63 79.5,48.39
VP3.3D on TOP (solid shape): outline of 1552 points within 0.56,8.13 37.86,54.44
VP3.3D on BOTTOM (solid shape): 74.68,5.72 74.68,1.08 74.5,0.9 70.89,0.9 70.74,1.05 70.74,3.02 70.27,3.49 65.6,3.49 65.25,3.14 64.11,3.14 64.03,3.21 64.03,4.32 64.03,5.66 64.03,5.66 64.03,5.92 64.11,6 74.4,6
VP3.3D on BOTTOM (solid shape): outline of 1013 points within 1.02,0.69 54.61,51.31
VP3.3D on ART03 (solid shape): outline of 1241 points within 16.51,9.84 39.91,40.13
VP+5V on BOTTOM (solid shape): 54.57,5.12 54.57,3.68 54.28,3.4 52.5,3.4 52.49,3.41 52.49,5.33 52.59,5.43 54.26,5.43
VP+5V on BOTTOM (solid shape): 12.06,32.94 12.23,32.94 12.38,32.79 12.38,31.72 12.38,31.71 12.38,31.08 11.38,30.08 11.38,28.27 11.21,28.1 10.53,28.1 10.35,28.27 10.35,30.2 9.99,30.56 6.5,30.56 6.16,30.21 6.16,28.21 6.1,28.15 5.24,28.15 5.15,28.24 5.15,30.23 4.83,30.56 2.9,30.56 2.69,30.76 2.69,32.61 3.03,32.95 12.05,32.95
VP+5V on ART03 (solid shape): outline of 6314 points within 0.56,0.56 82.23,54.44
VS+5V on ART03 (solid shape): outline of 886 points within 88.27,20.33 99.42,38.73
N16830570 on BOTTOM (solid shape): 47.92,5.33 47.92,2.88 47.71,2.66 45.17,2.66 44.81,3.03 44.81,5.08 45.19,5.46 47.8,5.46

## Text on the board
BOTTOM: ARTWORK BOTTOM
Board Geometry/Soldermask Bottom: SOLDERMASK BOTTOM
Package Geometry/Pastemask Bottom: PASTEMASK BOTTOM
Ref Des/Silkscreen Bottom: A | SILKSCREEN BOTTOM
TOP: ARTWORK TOP
Board Geometry/Soldermask Top: SOLDERMASK TOP
Package Geometry/Pastemask Top: PASTEMASK TOP
Ref Des/Silkscreen Top: B | A | REC 2038 | CRD22AD12N/CRD22DD12N Control board | SILKSCREEN TOP | - | +
ART02: ARTWORK LAYER02
ART03: ARTWORK LAYER03
DIMENSION: Board Cut Out | V-cut | FAB DRAWING
ASSEMBLY_TOP: PRIMARY SIDE
ASSEMBLY_BOTTOM: SECONDARY SIDE
User.7: ARTWORK LAYER03
User.9: ARTWORK LAYER02
User.21: FIGURE | SIZE | 12.0 | 32.0 | 35.0 | 39.0 | 40.0 | 45.0 | DRILL CHART: TOP to BOTTOM | ALL UNITS ARE IN MILS | PLATED | QTY | 508 | 2 | 6 | 48 | 7 | 14
